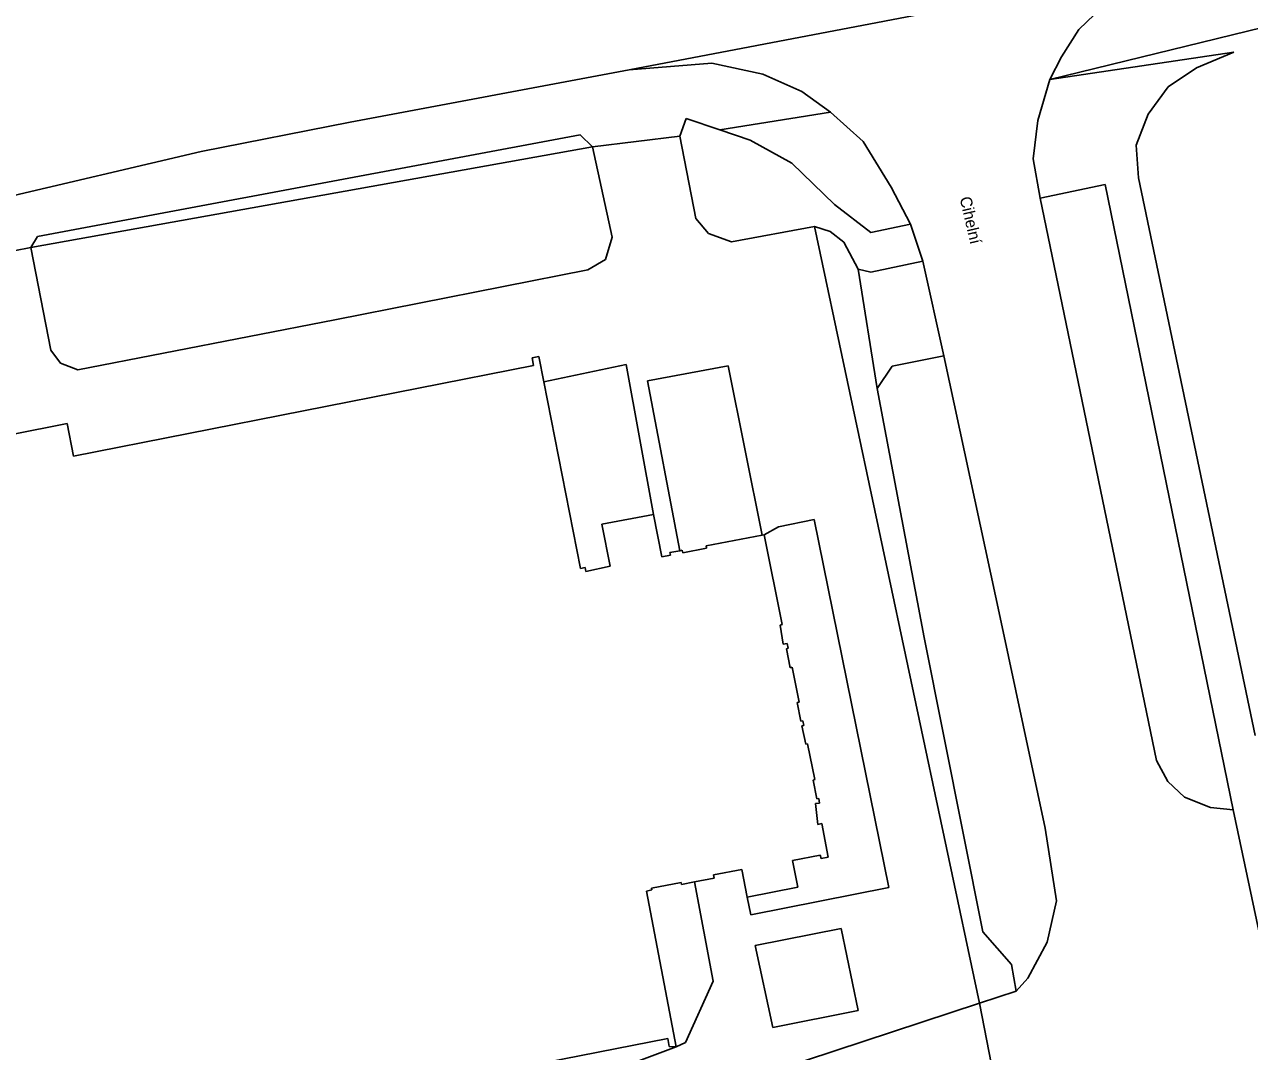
# Model space of a CAD drawing. Extents: x -452714 to -451134, y -1100194 to -1099694.
# Drawn here: x -452418.3 to -452344.3, y -1100036.5 to -1099974.5 of the extents above; entities that cross this region are included whole.
import ezdxf

# ---------------------------------------------------------------- set-up
doc = ezdxf.new("R2010")
doc.units = 0
doc.layers.add('Polohopis', color=7, linetype='Continuous')

msp = doc.modelspace()

# ---------------------------------------------------------------- linework, layer by layer
at = {"layer": 'Polohopis'}
for p, q in [((-452356.4, -1099977.87), (-452319.26, -1099968.8)), ((-452356.4, -1099977.87), (-452319.26, -1099968.8)), ((-452346.92, -1099970.62), (-452381.8, -1099977.29)), ((-452346.92, -1099970.62), (-452381.8, -1099977.29)), ((-452352.77, -1099973.03), (-452354.64, -1099974.85)), ((-452352.77, -1099973.03), (-452354.64, -1099974.85)), ((-452354.64, -1099974.85), (-452355.68, -1099976.5)), ((-452354.64, -1099974.85), (-452355.68, -1099976.5)), ((-452356.4, -1099977.87), (-452345.29, -1099976.22)), ((-452356.4, -1099977.87), (-452345.29, -1099976.22)), ((-452355.68, -1099976.5), (-452356.4, -1099977.87)), ((-452355.68, -1099976.5), (-452356.4, -1099977.87)), ((-452345.29, -1099976.22), (-452347.54, -1099977.16)), ((-452345.29, -1099976.22), (-452347.54, -1099977.16)), ((-452381.8, -1099977.29), (-452398.65, -1099980.45)), ((-452381.8, -1099977.29), (-452398.65, -1099980.45)), ((-452381.8, -1099977.29), (-452376.8, -1099976.88)), ((-452381.8, -1099977.29), (-452376.8, -1099976.88)), ((-452376.8, -1099976.88), (-452373.72, -1099977.54)), ((-452376.8, -1099976.88), (-452373.72, -1099977.54)), ((-452373.72, -1099977.54), (-452371.36, -1099978.59)), ((-452373.72, -1099977.54), (-452371.36, -1099978.59)), ((-452347.54, -1099977.16), (-452349.25, -1099978.31)), ((-452347.54, -1099977.16), (-452349.25, -1099978.31)), ((-452357.11, -1099980.35), (-452356.4, -1099977.87)), ((-452357.11, -1099980.35), (-452356.4, -1099977.87)), ((-452371.36, -1099978.59), (-452369.64, -1099979.83)), ((-452371.36, -1099978.59), (-452369.64, -1099979.83)), ((-452349.25, -1099978.31), (-452350.46, -1099979.96)), ((-452349.25, -1099978.31), (-452350.46, -1099979.96)), ((-452398.65, -1099980.45), (-452407.63, -1099982.22)), ((-452398.65, -1099980.45), (-452407.63, -1099982.22)), ((-452378.74, -1099981.29), (-452378.36, -1099980.22)), ((-452378.74, -1099981.29), (-452378.36, -1099980.22)), ((-452378.36, -1099980.22), (-452376.32, -1099980.9)), ((-452378.36, -1099980.22), (-452376.32, -1099980.9)), ((-452376.32, -1099980.9), (-452369.64, -1099979.83)), ((-452376.32, -1099980.9), (-452369.64, -1099979.83)), ((-452369.64, -1099979.83), (-452367.67, -1099981.61)), ((-452369.64, -1099979.83), (-452367.67, -1099981.61)), ((-452357.39, -1099982.66), (-452357.11, -1099980.35)), ((-452357.39, -1099982.66), (-452357.11, -1099980.35)), ((-452350.46, -1099979.96), (-452351.17, -1099981.83)), ((-452350.46, -1099979.96), (-452351.17, -1099981.83)), ((-452384.76, -1099981.2), (-452417.52, -1099987.35)), ((-452384.76, -1099981.2), (-452417.52, -1099987.35)), ((-452384, -1099981.94), (-452384.76, -1099981.2)), ((-452384, -1099981.94), (-452384.76, -1099981.2)), ((-452376.32, -1099980.9), (-452374.49, -1099981.52)), ((-452376.32, -1099980.9), (-452374.49, -1099981.52)), ((-452417.93, -1099988.01), (-452384, -1099981.94)), ((-452417.93, -1099988.01), (-452384, -1099981.94)), ((-452384, -1099981.94), (-452378.74, -1099981.29)), ((-452384, -1099981.94), (-452378.74, -1099981.29)), ((-452384, -1099981.94), (-452382.82, -1099987.39)), ((-452384, -1099981.94), (-452382.82, -1099987.39)), ((-452378.74, -1099981.29), (-452377.76, -1099986.26)), ((-452378.74, -1099981.29), (-452377.76, -1099986.26)), ((-452374.49, -1099981.52), (-452371.98, -1099982.92)), ((-452374.49, -1099981.52), (-452371.98, -1099982.92)), ((-452367.67, -1099981.61), (-452365.97, -1099984.36)), ((-452367.67, -1099981.61), (-452365.97, -1099984.36)), ((-452351.17, -1099981.83), (-452351.04, -1099983.8)), ((-452351.17, -1099981.83), (-452351.04, -1099983.8)), ((-452407.63, -1099982.22), (-452438.32, -1099989.41)), ((-452407.63, -1099982.22), (-452438.32, -1099989.41)), ((-452356.97, -1099985.02), (-452357.39, -1099982.66)), ((-452356.97, -1099985.02), (-452357.39, -1099982.66)), ((-452371.98, -1099982.92), (-452369.4, -1099985.41)), ((-452371.98, -1099982.92), (-452369.4, -1099985.41)), ((-452351.04, -1099983.8), (-452344, -1100017.46)), ((-452351.04, -1099983.8), (-452344, -1100017.46)), ((-452365.97, -1099984.36), (-452364.8, -1099986.6)), ((-452365.97, -1099984.36), (-452364.8, -1099986.6)), ((-452353.05, -1099984.21), (-452356.97, -1099985.02)), ((-452353.05, -1099984.21), (-452356.97, -1099985.02)), ((-452345.33, -1100021.95), (-452353.05, -1099984.21)), ((-452345.33, -1100021.95), (-452353.05, -1099984.21)), ((-452369.4, -1099985.41), (-452367.21, -1099987.11)), ((-452369.4, -1099985.41), (-452367.21, -1099987.11)), ((-452349.96, -1100018.98), (-452356.97, -1099985.02)), ((-452349.96, -1100018.98), (-452356.97, -1099985.02)), ((-452377.76, -1099986.26), (-452377, -1099987.17)), ((-452377.76, -1099986.26), (-452377, -1099987.17)), ((-452375.61, -1099987.66), (-452370.6, -1099986.73)), ((-452375.61, -1099987.66), (-452370.6, -1099986.73)), ((-452370.6, -1099986.73), (-452360.64, -1100033.62)), ((-452370.6, -1099986.73), (-452369.65, -1099987.05)), ((-452370.6, -1099986.73), (-452360.64, -1100033.62)), ((-452370.6, -1099986.73), (-452369.65, -1099987.05)), ((-452369.65, -1099987.05), (-452368.84, -1099987.69)), ((-452369.65, -1099987.05), (-452368.84, -1099987.69)), ((-452367.21, -1099987.11), (-452364.8, -1099986.6)), ((-452367.21, -1099987.11), (-452364.8, -1099986.6)), ((-452364.8, -1099986.6), (-452364.06, -1099988.83)), ((-452364.8, -1099986.6), (-452364.06, -1099988.83)), ((-452417.52, -1099987.35), (-452417.93, -1099988.01)), ((-452417.52, -1099987.35), (-452417.93, -1099988.01)), ((-452382.82, -1099987.39), (-452383.23, -1099988.74)), ((-452382.82, -1099987.39), (-452383.23, -1099988.74)), ((-452377, -1099987.17), (-452375.61, -1099987.66)), ((-452377, -1099987.17), (-452375.61, -1099987.66)), ((-452368.84, -1099987.69), (-452367.96, -1099989.31)), ((-452368.84, -1099987.69), (-452367.96, -1099989.31)), ((-452421.53, -1099988.71), (-452417.93, -1099988.01)), ((-452421.53, -1099988.71), (-452417.93, -1099988.01)), ((-452416.71, -1099994.21), (-452417.93, -1099988.01)), ((-452416.71, -1099994.21), (-452417.93, -1099988.01)), ((-452384.28, -1099989.35), (-452399.57, -1099992.37)), ((-452384.28, -1099989.35), (-452399.57, -1099992.37)), ((-452383.23, -1099988.74), (-452384.28, -1099989.35)), ((-452383.23, -1099988.74), (-452384.28, -1099989.35)), ((-452367.96, -1099989.31), (-452366.82, -1099996.51)), ((-452367.21, -1099989.49), (-452367.96, -1099989.31)), ((-452367.96, -1099989.31), (-452366.82, -1099996.51)), ((-452367.21, -1099989.49), (-452367.96, -1099989.31)), ((-452364.06, -1099988.83), (-452367.21, -1099989.49)), ((-452364.06, -1099988.83), (-452367.21, -1099989.49)), ((-452364.06, -1099988.83), (-452362.79, -1099994.54)), ((-452364.06, -1099988.83), (-452362.79, -1099994.54)), ((-452399.57, -1099992.37), (-452415.08, -1099995.4)), ((-452399.57, -1099992.37), (-452415.08, -1099995.4)), ((-452416.14, -1099994.98), (-452416.71, -1099994.21)), ((-452416.14, -1099994.98), (-452416.71, -1099994.21)), ((-452362.79, -1099994.54), (-452365.92, -1099995.17)), ((-452362.79, -1099994.54), (-452365.92, -1099995.17)), ((-452362.79, -1099994.54), (-452359.34, -1100010.62)), ((-452362.79, -1099994.54), (-452359.34, -1100010.62)), ((-452415.08, -1099995.4), (-452416.14, -1099994.98)), ((-452415.08, -1099995.4), (-452416.14, -1099994.98)), ((-452415.34, -1100000.61), (-452387.57, -1099995.13)), ((-452415.34, -1100000.61), (-452387.57, -1099995.13)), ((-452387.66, -1099994.66), (-452387.25, -1099994.58)), ((-452387.66, -1099994.66), (-452387.25, -1099994.58)), ((-452387.57, -1099995.13), (-452387.66, -1099994.66)), ((-452387.57, -1099995.13), (-452387.66, -1099994.66)), ((-452387.25, -1099994.58), (-452386.95, -1099996.11)), ((-452387.25, -1099994.58), (-452386.95, -1099996.11)), ((-452386.95, -1099996.11), (-452381.98, -1099995.06)), ((-452386.95, -1099996.11), (-452381.98, -1099995.06)), ((-452381.98, -1099995.06), (-452380.32, -1100004.12)), ((-452381.98, -1099995.06), (-452380.32, -1100004.12)), ((-452380.68, -1099996.05), (-452375.81, -1099995.14)), ((-452380.68, -1099996.05), (-452375.81, -1099995.14)), ((-452375.81, -1099995.14), (-452373.76, -1100005.38)), ((-452375.81, -1099995.14), (-452373.76, -1100005.38)), ((-452365.92, -1099995.17), (-452366.82, -1099996.51)), ((-452365.92, -1099995.17), (-452366.82, -1099996.51)), ((-452386.95, -1099996.11), (-452384.74, -1100007.38)), ((-452386.95, -1099996.11), (-452384.74, -1100007.38)), ((-452378.74, -1100006.31), (-452380.68, -1099996.05)), ((-452378.74, -1100006.31), (-452380.68, -1099996.05)), ((-452366.82, -1099996.51), (-452363.97, -1100011.54)), ((-452366.82, -1099996.51), (-452363.97, -1100011.54)), ((-452419.07, -1099999.3), (-452415.73, -1099998.64)), ((-452419.07, -1099999.3), (-452415.73, -1099998.64)), ((-452415.73, -1099998.64), (-452415.34, -1100000.61)), ((-452415.73, -1099998.64), (-452415.34, -1100000.61)), ((-452383.44, -1100004.7), (-452380.32, -1100004.12)), ((-452383.44, -1100004.7), (-452380.32, -1100004.12)), ((-452380.32, -1100004.12), (-452379.82, -1100006.68)), ((-452380.32, -1100004.12), (-452379.82, -1100006.68)), ((-452382.94, -1100007.24), (-452383.44, -1100004.7)), ((-452382.94, -1100007.24), (-452383.44, -1100004.7)), ((-452373.64, -1100005.36), (-452372.78, -1100004.86)), ((-452373.64, -1100005.36), (-452372.78, -1100004.86)), ((-452372.78, -1100004.86), (-452370.62, -1100004.43)), ((-452372.78, -1100004.86), (-452370.62, -1100004.43)), ((-452370.62, -1100004.43), (-452366.12, -1100026.64)), ((-452370.62, -1100004.43), (-452366.12, -1100026.64)), ((-452377.14, -1100006.01), (-452373.76, -1100005.38)), ((-452377.14, -1100006.01), (-452373.76, -1100005.38)), ((-452373.76, -1100005.38), (-452373.64, -1100005.36)), ((-452373.76, -1100005.38), (-452373.64, -1100005.36)), ((-452373.64, -1100005.36), (-452372.55, -1100010.77)), ((-452373.64, -1100005.36), (-452372.55, -1100010.77)), ((-452379.33, -1100006.42), (-452378.74, -1100006.31)), ((-452379.33, -1100006.42), (-452378.74, -1100006.31)), ((-452378.74, -1100006.31), (-452378.59, -1100006.28)), ((-452378.74, -1100006.31), (-452378.59, -1100006.28)), ((-452378.59, -1100006.28), (-452378.56, -1100006.43)), ((-452378.59, -1100006.28), (-452378.56, -1100006.43)), ((-452378.56, -1100006.43), (-452377.12, -1100006.16)), ((-452378.56, -1100006.43), (-452377.12, -1100006.16)), ((-452377.12, -1100006.16), (-452377.14, -1100006.01)), ((-452377.12, -1100006.16), (-452377.14, -1100006.01)), ((-452379.82, -1100006.68), (-452379.3, -1100006.57)), ((-452379.82, -1100006.68), (-452379.3, -1100006.57)), ((-452379.3, -1100006.57), (-452379.33, -1100006.42)), ((-452379.3, -1100006.57), (-452379.33, -1100006.42)), ((-452384.74, -1100007.38), (-452384.44, -1100007.33)), ((-452384.74, -1100007.38), (-452384.44, -1100007.33)), ((-452384.44, -1100007.33), (-452384.4, -1100007.56)), ((-452384.44, -1100007.33), (-452384.4, -1100007.56)), ((-452384.4, -1100007.56), (-452382.94, -1100007.24)), ((-452384.4, -1100007.56), (-452382.94, -1100007.24)), ((-452372.55, -1100010.77), (-452372.67, -1100010.8)), ((-452372.55, -1100010.77), (-452372.67, -1100010.8)), ((-452372.67, -1100010.8), (-452372.49, -1100011.96)), ((-452372.67, -1100010.8), (-452372.49, -1100011.96)), ((-452359.34, -1100010.62), (-452356.68, -1100023.05)), ((-452359.34, -1100010.62), (-452356.68, -1100023.05)), ((-452363.97, -1100011.54), (-452360.44, -1100029.31)), ((-452363.97, -1100011.54), (-452360.44, -1100029.31)), ((-452372.49, -1100011.96), (-452372.25, -1100011.91)), ((-452372.49, -1100011.96), (-452372.25, -1100011.91)), ((-452372.19, -1100012.2), (-452372.3, -1100012.23)), ((-452372.19, -1100012.2), (-452372.3, -1100012.23)), ((-452372.3, -1100012.23), (-452372.07, -1100013.38)), ((-452372.3, -1100012.23), (-452372.07, -1100013.38)), ((-452372.25, -1100011.91), (-452372.19, -1100012.2)), ((-452372.25, -1100011.91), (-452372.19, -1100012.2)), ((-452372.07, -1100013.38), (-452371.95, -1100013.35)), ((-452372.07, -1100013.38), (-452371.95, -1100013.35)), ((-452371.95, -1100013.35), (-452371.53, -1100015.45)), ((-452371.95, -1100013.35), (-452371.53, -1100015.45)), ((-452371.53, -1100015.45), (-452371.64, -1100015.47)), ((-452371.53, -1100015.45), (-452371.64, -1100015.47)), ((-452371.64, -1100015.47), (-452371.42, -1100016.6)), ((-452371.64, -1100015.47), (-452371.42, -1100016.6)), ((-452371.42, -1100016.6), (-452371.3, -1100016.57)), ((-452371.42, -1100016.6), (-452371.3, -1100016.57)), ((-452371.3, -1100016.57), (-452371.24, -1100016.86)), ((-452371.3, -1100016.57), (-452371.24, -1100016.86)), ((-452371.24, -1100016.86), (-452371.36, -1100016.88)), ((-452371.24, -1100016.86), (-452371.36, -1100016.88)), ((-452371.36, -1100016.88), (-452371.13, -1100017.99)), ((-452371.36, -1100016.88), (-452371.13, -1100017.99)), ((-452371.13, -1100017.99), (-452371.02, -1100017.97)), ((-452371.13, -1100017.99), (-452371.02, -1100017.97)), ((-452371.02, -1100017.97), (-452370.58, -1100020.13)), ((-452371.02, -1100017.97), (-452370.58, -1100020.13)), ((-452349.27, -1100020.25), (-452349.96, -1100018.98)), ((-452349.27, -1100020.25), (-452349.96, -1100018.98)), ((-452370.58, -1100020.13), (-452370.69, -1100020.16)), ((-452370.58, -1100020.13), (-452370.69, -1100020.16)), ((-452370.69, -1100020.16), (-452370.47, -1100021.28)), ((-452370.69, -1100020.16), (-452370.47, -1100021.28)), ((-452348.25, -1100021.19), (-452349.27, -1100020.25)), ((-452348.25, -1100021.19), (-452349.27, -1100020.25)), ((-452370.29, -1100021.54), (-452370.54, -1100021.57)), ((-452370.29, -1100021.54), (-452370.54, -1100021.57)), ((-452370.54, -1100021.57), (-452370.4, -1100022.83)), ((-452370.54, -1100021.57), (-452370.4, -1100022.83)), ((-452370.47, -1100021.28), (-452370.35, -1100021.26)), ((-452370.47, -1100021.28), (-452370.35, -1100021.26)), ((-452370.35, -1100021.26), (-452370.29, -1100021.54)), ((-452370.35, -1100021.26), (-452370.29, -1100021.54)), ((-452346.68, -1100021.82), (-452348.25, -1100021.19)), ((-452346.68, -1100021.82), (-452348.25, -1100021.19)), ((-452345.33, -1100021.95), (-452346.68, -1100021.82)), ((-452345.33, -1100021.95), (-452346.68, -1100021.82)), ((-452340.09, -1100046.67), (-452345.33, -1100021.95)), ((-452340.09, -1100046.67), (-452345.33, -1100021.95)), ((-452370.4, -1100022.83), (-452370.16, -1100022.78)), ((-452370.4, -1100022.83), (-452370.16, -1100022.78)), ((-452370.16, -1100022.78), (-452369.77, -1100024.8)), ((-452370.16, -1100022.78), (-452369.77, -1100024.8)), ((-452356.68, -1100023.05), (-452355.99, -1100027.44)), ((-452356.68, -1100023.05), (-452355.99, -1100027.44)), ((-452370.26, -1100024.68), (-452371.94, -1100025.02)), ((-452370.26, -1100024.68), (-452371.94, -1100025.02)), ((-452370.19, -1100024.88), (-452370.26, -1100024.68)), ((-452370.19, -1100024.88), (-452370.26, -1100024.68)), ((-452369.77, -1100024.8), (-452370.19, -1100024.88)), ((-452369.77, -1100024.8), (-452370.19, -1100024.88)), ((-452374.98, -1100025.55), (-452376.7, -1100025.88)), ((-452374.98, -1100025.55), (-452376.7, -1100025.88)), ((-452374.66, -1100027.23), (-452374.98, -1100025.55)), ((-452374.66, -1100027.23), (-452374.98, -1100025.55)), ((-452371.94, -1100025.02), (-452371.61, -1100026.62)), ((-452371.94, -1100025.02), (-452371.61, -1100026.62)), ((-452378.66, -1100026.33), (-452380.45, -1100026.68)), ((-452378.66, -1100026.33), (-452380.45, -1100026.68)), ((-452378.63, -1100026.45), (-452378.66, -1100026.33)), ((-452378.63, -1100026.45), (-452378.66, -1100026.33)), ((-452377.84, -1100026.3), (-452378.63, -1100026.45)), ((-452377.84, -1100026.3), (-452378.63, -1100026.45)), ((-452376.66, -1100026.08), (-452377.84, -1100026.3)), ((-452376.66, -1100026.08), (-452377.84, -1100026.3)), ((-452377.84, -1100026.3), (-452376.72, -1100032.3)), ((-452377.84, -1100026.3), (-452376.72, -1100032.3)), ((-452376.7, -1100025.88), (-452376.66, -1100026.08)), ((-452376.7, -1100025.88), (-452376.66, -1100026.08)), ((-452380.43, -1100026.79), (-452380.75, -1100026.87)), ((-452380.43, -1100026.79), (-452380.75, -1100026.87)), ((-452380.75, -1100026.87), (-452378.95, -1100036.26)), ((-452380.75, -1100026.87), (-452378.95, -1100036.26)), ((-452380.45, -1100026.68), (-452380.43, -1100026.79)), ((-452380.45, -1100026.68), (-452380.43, -1100026.79)), ((-452371.61, -1100026.62), (-452374.66, -1100027.23)), ((-452371.61, -1100026.62), (-452374.66, -1100027.23)), ((-452366.12, -1100026.64), (-452374.45, -1100028.3)), ((-452366.12, -1100026.64), (-452374.45, -1100028.3)), ((-452374.45, -1100028.3), (-452374.66, -1100027.23)), ((-452374.45, -1100028.3), (-452374.66, -1100027.23)), ((-452355.99, -1100027.44), (-452356.55, -1100029.94)), ((-452355.99, -1100027.44), (-452356.55, -1100029.94)), ((-452374.18, -1100030.15), (-452368.99, -1100029.11)), ((-452374.18, -1100030.15), (-452368.99, -1100029.11)), ((-452368.99, -1100029.11), (-452367.97, -1100034.06)), ((-452368.99, -1100029.11), (-452367.97, -1100034.06)), ((-452360.44, -1100029.31), (-452358.7, -1100031.28)), ((-452360.44, -1100029.31), (-452358.7, -1100031.28)), ((-452356.55, -1100029.94), (-452357.72, -1100032.12)), ((-452356.55, -1100029.94), (-452357.72, -1100032.12)), ((-452373.11, -1100035.09), (-452374.18, -1100030.15)), ((-452373.11, -1100035.09), (-452374.18, -1100030.15)), ((-452358.7, -1100031.28), (-452358.42, -1100032.89)), ((-452358.7, -1100031.28), (-452358.42, -1100032.89)), ((-452357.72, -1100032.12), (-452358.42, -1100032.89)), ((-452357.72, -1100032.12), (-452358.42, -1100032.89)), ((-452376.72, -1100032.3), (-452378.39, -1100035.99)), ((-452376.72, -1100032.3), (-452378.39, -1100035.99)), ((-452358.42, -1100032.89), (-452360.64, -1100033.62)), ((-452358.42, -1100032.89), (-452360.64, -1100033.62)), ((-452360.64, -1100033.62), (-452394.13, -1100044.63)), ((-452360.64, -1100033.62), (-452394.13, -1100044.63)), ((-452359.92, -1100037.34), (-452360.64, -1100033.62)), ((-452359.92, -1100037.34), (-452360.64, -1100033.62)), ((-452367.97, -1100034.06), (-452373.11, -1100035.09)), ((-452367.97, -1100034.06), (-452373.11, -1100035.09)), ((-452379.46, -1100035.75), (-452407.29, -1100041.2)), ((-452379.46, -1100035.75), (-452407.29, -1100041.2)), ((-452379.38, -1100036.23), (-452379.46, -1100035.75)), ((-452379.38, -1100036.23), (-452379.46, -1100035.75)), ((-452378.95, -1100036.26), (-452406.31, -1100046.47)), ((-452378.95, -1100036.26), (-452406.31, -1100046.47)), ((-452378.95, -1100036.26), (-452379.38, -1100036.23)), ((-452378.95, -1100036.26), (-452379.38, -1100036.23)), ((-452378.39, -1100035.99), (-452378.95, -1100036.26)), ((-452378.39, -1100035.99), (-452378.95, -1100036.26))]:
    msp.add_line(p, q, dxfattribs=at)

# ---------------------------------------------------------------- texts
msp.add_text('Cihelní', height=0.7, rotation=283, dxfattribs=at).set_placement((-452361.84, -1099985.02))
msp.add_text('Cihelní', height=0.7, rotation=283, dxfattribs=at).set_placement((-452361.84, -1099985.02))

doc.saveas('drawing.dxf')
